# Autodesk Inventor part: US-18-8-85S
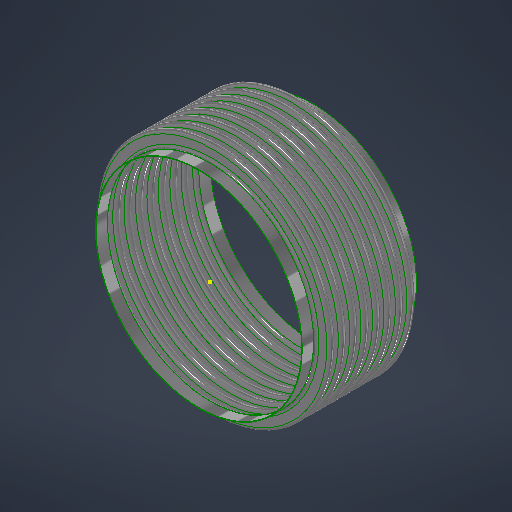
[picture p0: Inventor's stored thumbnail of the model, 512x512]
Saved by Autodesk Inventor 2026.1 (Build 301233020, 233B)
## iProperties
Category: 18 GA (0.048 THICK)
RuleStatus: InUse
Created: 2026-07
Part Number: US-18-8-85S
Project: =STOCK BELLOWS: <Stock Number><SFILL>
Material: ASTM A240-304
Description: =STOCK BELLOWS: <Stock Number>, <SID_> I.D., <SOD_> O.D., <SPLY_> PLY, <Category>, <SNET_CONS> CONS.<PITCH_><STANGENT_> TANGENT<SFILL>
Document SubType Name: Sheet Metal
Designer: LC
Stock Number: U.S-18-8-85S
Surface Area: 659.127 cm^2
Volume: 56.61 cm^3
Sheet Metal Rule: Default
Appearance: STAINLESS STEEL
NET_TUBE: 3.428
COUNTER: 1.500
PBAR: 1.214
PSET: 5.356
PLY: 2
CONS: 2
THK: 0.036
ID: 4.500
OD: 5.500
CONS_: 2
TANGENT: 0.500
PITCH: 0.375
BELLOWS_UPSET: 0.000
NET_CONS: 2
S_CONS: 0
Description_Units: 0
ID_M: 114.30 mm
OD_M: 139.70 mm
THK_M: 0.91 mm
ID_U: 4.500 in
OD_U: 5.500 in
THK_U: 0.036 in
TANGENT2: 0.500
d79: 1.000
d82: 1.000
d83: 26.000
d84: 24.000
d80: 2.571
d81: 10
SID: 2.375
SCONS_: 8
SPITCH: 0.250
SBELLOWS_UPSET: 0.000
SNET_CONS: 8
SS_CONS: 0
SCONS: 8
d174: 8
d177: 0.018
d178: 2.375
d179: 3.000
d180: 0.375
d181: 1.000
d182: 0.000
d190: 8
d191: 1
d192: 1
d193: 8
d194: 0
PART_NUMBER: U.S-18-8-85S
PRESSURE: 85
SIZE: 18.00
STANGENT_: 1.000
d214: 8
d217: 0.030
d218: 6.625
d219: 8.125
d220: 0.500
d221: 1.000
d222: 0.000
d230: 8
d231: 1
d232: 1
d233: 8
d234: 0
STANGENT: 4.000
SPLY_: 1
STHK_: 0.048
SID_: 18.000
SOD_: 20.500
SPITCH_: 1.000
STANGENT__: 1.000
SBELLOWS_UPSET_: 0.000
SDIFF_TAN: 1.000
TAN_TO_TAN: 0.750 in
d252: 2
d275: 2
d287: 0.050
d289: 0.500
d290: 0.000
d263: 2
d265: 1
d268: 2
d269: 0
d286: 2
d288: 1
d291: 2
d292: 0
SOD_NECK: 18 1/8
CFILL: .
SFILL: .
PITCH_: =, <SPITCH_> PITCH,
SREROLL: 0.750
MATTABLE: 20 GA (0.036 THICK)
MESH: ,
CSECT: 2
Author: LC
Keywords: 20 GA (0.036 THICK)
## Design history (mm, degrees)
sketch "Sketch2"
  geometry: L1 (0, -183.595)-(0, 600.956) reference; L2 (58.979, 0)-(57.15, 0); L3 (60.446, -1.467)-(66.554, -1.467); L4 (60.446, -3.296)-(66.554, -3.296); L5 (66.554, -8.058)-(60.446, -8.058); L6 (66.554, -6.229)-(60.446, -6.229); L7 (58.979, -9.525)-(57.15, -9.525); L8 (60.446, 0)-(60.446, -9.525); L9 (66.554, -4.762)-(69.85, -4.763); L10 (57.15, 0)-(57.15, -9.525); L11 (20.376, 102.841)-(20.376, 101.926); L12 (58.262, 488.877)-(58.262, 349.177); L13 (58.262, 479.352)-(58.262, 339.652); L14 (93.133, -58.817)-(93.133, -71.517); L15 (118.746, -66.401)-(118.746, -66.401); L16 (66.554, -6.229)-(66.554, -8.058); L17 (60.446, -6.229)-(60.446, -8.058); L18 (60.446, -7.144)-(66.554, -7.144); L19 (69.85, 0)-(69.85, -9.525); L20 (-66.554, -6.229)-(-66.554, -8.058); L21 (-66.554, -1.467)-(-60.446, -1.467); L22 (-66.554, -3.296)-(-60.446, -3.296); L23 (-60.446, -6.229)-(-66.554, -6.229); L24 (-66.554, -7.144)-(-60.446, -7.144); L25 (-60.446, -8.058)-(-66.554, -8.058); L26 (-60.446, -6.229)-(-60.446, -8.058); L27 (-57.15, -2.522)-(-57.15, -12.047); L28 (-60.446, -4.763)-(-57.15, -4.763); L29 (-66.554, 3.828)-(-66.554, -9.525); L30 (-68.021, 0)-(-69.85, 0); L31 (-69.85, 0)-(-69.85, -9.525); L32 (-68.021, -9.525)-(-69.85, -9.525); A1 r 1.467 centre (60.446, 0) between (58.979, 0) and (60.446, -1.467); A2 r 3.296 centre (60.446, 0) between (57.15, 0) and (60.446, -3.296); A3 r 3.296 centre (66.554, -4.762) between (66.554, -8.058) and (66.554, -1.467); A4 r 1.467 centre (66.554, -4.762) between (66.554, -6.229) and (66.554, -3.296); A5 r 1.467 centre (60.446, -9.525) between (60.446, -8.058) and (58.979, -9.525); A6 r 3.296 centre (60.446, -9.525) between (60.446, -6.229) and (57.15, -9.525); A7 r 2.381 centre (66.554, -4.762) between (66.554, -7.144) and (68.936, -4.762); A8 r 2.381 centre (60.446, -9.525) between (60.446, -7.144) and (58.064, -9.525); A9 r 1.467 centre (-66.554, -9.525) between (-66.554, -8.058) and (-68.021, -9.525); A10 r 1.467 centre (-60.446, -4.763) between (-60.446, -6.229) and (-60.446, -3.296); A11 r 2.381 centre (-60.446, -4.763) between (-60.446, -7.144) and (-58.064, -4.763); A12 r 3.296 centre (-60.446, -4.763) between (-60.446, -8.058) and (-60.446, -1.467); A13 r 2.381 centre (-66.554, -9.525) between (-66.554, -7.144) and (-68.936, -9.525); A14 r 3.296 centre (-66.554, -9.525) between (-66.554, -6.229) and (-69.85, -9.525); A15 r 1.467 centre (-66.554, 0) between (-68.021, 0) and (-66.554, -1.467); A16 r 3.296 centre (-66.554, 0) between (-69.85, 0) and (-66.554, -3.296); 10 further points
  constraints: 62 end point, 38 point on circle, 20 tangent, 16 centre point, 12 parallel, 9 midpoint, 7 vertical, 6 coincident, 6 concentric, 6 point on line, 4 equal radius, 4 perpendicular, 3 horizontal, 1 collinear, 1 horizontal alignment, 10 other
  dimensions: "THK" = 0.9144 distance of L11.start L11.end; "ID" = 114.3 distance of L11.end point (20.376, -12.374); "OD" = 139.7 distance of L12.start L12.end; "PITCH" = 9.525 distance of L12.start L13.start; "TANGENT" = 12.7 distance of L14.start L14.end; "BELLOWS_UPSET" = 0 distance of L15.start L15.end; "d43" = 114.3 diameter of L10 L1 (= ID); "d44" = 139.7 diameter of L9.end L1 (= OD); "d45" = 1.8288 distance between parallel lines of L5 L6 (computed from THK, PLY); "d46" = 3.29565 radius of A3 (computed from PITCH, THK, PLY); "UPSET_PITCH" = 9.525 distance of L2.end L7.end (derived); "SIDEWALL_ANGLE" = 0 deg angle of L3 L9 (derived); "CON_GAP" = 2.9337 distance of point (60.446, -6.229) point (60.446, -3.296) (derived); "TAN1" = 3.74046 dimension on A8 (derived); "TAN2" = 3.74046 dimension on A7 (derived); "LEG1" = 6.1087 distance of L18.start L18.end (derived); "d278" = 1.8288 distance between parallel lines of L25 L23 (derived); "d279" = 3.29565 radius of A12 (derived); "d280" = 9.525 distance of L30.end L31.end (derived); "d281" = 360 deg dimension on L21 L28 (derived); "d282" = 2.9337 distance of point (-66.554, -6.229) point (-66.554, -3.296) (derived); "d283" = 3.74046 dimension on A13 (derived); "d284" = 3.74046 dimension on A11 (derived); "d285" = 6.1087 distance of L24.start L24.end (derived); "d293" = 114.3 diameter of L27 L1 (derived); "d294" = 139.7 diameter of L31 L1 (derived)
  node "Sketch Rectangular Pattern1" dims "d31" = 25.4, "ID" = 114.3
  node "Sketch Rectangular Pattern2" dims "d39" = 25.4, "PITCH" = 9.525
revolve "CONS" stored, may be unused: angle "d48" = 90 deg
node "BELLOW MIDPLANE"
pattern_linear "Rectangular Pattern2" dims "d52" = 9.525 (= UPSET_PITCH)
sketch "Sketch5"
  geometry: C1 r 58.979 at (0, 0) reference; C2 r 57.15 at (0, 0) reference
extrude "TANGENT" new body sketch "Sketch5" distance "d53" = 12.7 (= TANGENT); taper "d54" = 0 deg
revolve "SAMETAN" stored, may be unused: angle "d65" = 90 deg
revolve "DIFFTAN" stored, may be unused: angle "d70" = 90 deg
sketch "Sketch9"
  geometry: L1 (58.391, 0)-(-58.391, 0) reference; L2 (0, -17.78)-(0, 17.78) reference; L3 (41.708, 0)-(-41.708, 0); L4 (41.708, -11.906)-(41.708, 11.906); L5 (29.008, -11.906)-(29.008, 11.906); L6 (15.418, 11.906)-(15.418, -11.906); L7 (-29.008, -11.906)-(-29.008, 11.906); L8 (-41.708, -11.906)-(-41.708, 11.906); L9 (40.914, -11.906)-(40.914, 11.906); L10 (41.708, -11.906)-(40.914, -11.906); L11 (41.708, 11.906)-(40.914, 11.906); L12 (15.815, 11.906)-(15.022, 11.906); L13 (15.022, 11.906)-(15.022, -11.906); L14 (15.022, -11.906)-(15.815, -11.906); L15 (15.815, -11.906)-(15.815, 11.906); L16 (-15.815, 11.906)-(-15.815, -11.906); L17 (-15.418, 11.906)-(-15.418, -11.906); L18 (-15.815, -11.906)-(-15.022, -11.906); L19 (-15.022, -11.906)-(-15.022, 11.906); L20 (-15.022, 11.906)-(-15.815, 11.906); L21 (-41.708, -11.906)-(-40.914, -11.906); L22 (-40.914, -11.906)-(-40.914, 11.906); L23 (-40.914, 11.906)-(-41.708, 11.906); L24 (-41.708, 11.906)-(-41.708, -11.906); L25 (41.708, -0.397)-(-41.708, -0.397); L26 (-41.708, -0.397)-(-41.708, 0.397); L27 (-41.708, 0.397)-(41.708, 0.397); L28 (41.708, 0.397)-(41.708, -0.397); L29 (-41.708, 11.906)-(41.708, 11.906); L30 (41.708, 11.906)-(41.708, 12.7); L31 (41.708, 12.7)-(-41.708, 12.7); L32 (-41.708, 12.7)-(-41.708, 11.906); L33 (41.708, -11.906)-(-41.708, -11.906); L34 (-41.708, -11.906)-(-41.708, -12.7); L35 (-41.708, -12.7)-(41.708, -12.7); L36 (41.708, -12.7)-(41.708, -11.906); 30 further points
  constraints: 68 end point, 13 midpoint, 13 parallel, 8 horizontal, 7 perpendicular, 6 equal length, 3 point on line, 2 vertical, 14 other
  dimensions: "d115" = 23.8125 distance of L4.start L4.end (derived); "d116" = 12.7 distance between parallel lines of L4 L5 (derived); "d117" = 13.58962 distance between parallel lines of L5 L6 (derived); "d125" = 44.42645 distance between parallel lines of L7 L6 (derived); "d127" = 12.7 distance between parallel lines of L8 L7 (derived); "d128" = 26.28962 distance between parallel lines of L6 L4 (derived); "d130" = 83.41607 distance between parallel lines of L8 L4 (derived); "RULER_THK" = 0.79375 distance between parallel lines of L4 L9; "d135" = 0.79375 distance of L13.end L14.end (derived); "d138" = 30.83684 distance of L13.end L16.end (derived); "d143" = 0.79375 distance of L22.end L8.end (derived); "d144" = 0.79375 distance between parallel lines of L27 L25 (derived)
extrude "RULER" join sketch "Sketch9" distance "d149" = 0.79375 (derived); taper "d150" = 0 deg
extrude "BARS" join sketch "Sketch9" distance "d151" = 0.79375 (derived); taper "d152" = 0 deg
pattern_linear "Rectangular Pattern4" dims "d155" = 30.83684 (derived)
sketch "Sketch13"
  geometry: L1 (93.149, -52.467)-(93.149, -77.867); L2 (229.819, 0)-(228.6, 0); L3 (229.819, -25.4)-(228.6, -25.4); L4 (253.39, -19.66)-(235.56, -19.66); L5 (253.39, -18.44)-(235.56, -18.44); L6 (253.39, -12.7)-(260.35, -12.7); L7 (235.56, -5.74)-(253.39, -5.74); L8 (235.56, 0)-(235.56, -25.4); L9 (228.6, 0)-(228.6, -25.4); L10 (58.254, -220.206)-(58.254, -740.906); L11 (58.254, -245.606)-(58.254, -766.306); L12 (58.254, -296.406)-(58.254, -817.106); L13 (58.254, -321.806)-(58.254, -842.506); L14 (58.254, -347.206)-(58.254, -867.906); L15 (58.254, -372.606)-(58.254, -893.306); L16 (58.254, -398.006)-(58.254, -918.706); L17 (58.254, -271.006)-(58.254, -791.706); L18 (20.376, 103.145)-(20.376, 101.926); L19 (235.56, -6.96)-(253.39, -6.96); L20 (0, -1082.436)-(0, 300.742) reference; L21 (-46.99, 0)-(281.94, 0) reference; A1 r 5.74 centre (235.56, 0) between (229.819, 0) and (235.56, -5.74); A2 r 5.74 centre (235.56, -25.4) between (235.56, -19.66) and (229.819, -25.4); A3 r 6.96 centre (235.56, -25.4) between (235.56, -18.44) and (228.6, -25.4); A4 r 5.74 centre (253.39, -12.7) between (253.39, -18.44) and (253.39, -6.96); A5 r 6.96 centre (253.39, -12.7) between (253.39, -19.66) and (253.39, -5.74); A6 r 6.96 centre (235.56, 0) between (228.6, 0) and (235.56, -6.96); 6 further points; 1 other entity
  constraints: 38 end point, 15 point on circle, 9 tangent, 6 centre point, 6 parallel, 5 vertical alignment, 4 point on line, 4 vertical, 3 coincident, 3 concentric, 2 collinear, 2 equal radius, 1 horizontal, 1 perpendicular, 23 other
  dimensions: "SBELLOWS_UPSET_" = 0 distance of point (118.762, -66.401) point (118.762, -66.401); "STOTAL_THK_BELLOW__" = 1.2192 distance between parallel lines of L4 L5 (derived); "d224" = 6.9596 radius of A5 (derived); "d225" = 25.4 distance of L2.end L3.end (derived); "SSIDEWALL_ANGLE_" = 360 deg dimension on L7 L6 (derived); "SSCON_GAP_" = 11.4808 distance of point (235.56, -18.44) point (235.56, -6.96) (derived); "d235" = 457.2 diameter of L9 L20 (derived); "d236" = 520.7 diameter of L6.end L20 (derived)
  node "Sketch Rectangular Pattern4" dims "d228" = 25.4
  node "Sketch Rectangular Pattern5" dims "d229" = 25.4
revolve "SBELLOW" stored, may be unused: angle "d197" = 90 deg
pattern_linear "Rectangular Pattern5" dims "d204" = 25.4 (derived)
revolve "STANGENT" stored, may be unused: angle "d240" = 90 deg
revolve "SSAMETAN" stored, may be unused: angle "d241" = 90 deg
revolve "SDIFFTAN" stored, may be unused: angle "d246" = 90 deg
revolve "INVCON" stored, may be unused: angle "d295" = 90 deg
pattern_linear "Rectangular Pattern6" dims "d298" = 9.525 (derived)
revolve "INVTANGENT" stored, may be unused: angle "d302" = 90 deg
revolve "INVSAMETAN" stored, may be unused: angle "d307" = 90 deg
revolve "INVDIFFTAN" stored, may be unused: angle "d312" = 90 deg
sketch "ID BELLOW MOUNT CALC"
  geometry: L1 (44.45, 0)-(38.1, 0); L2 (38.1, 0)-(38.1, 12.7); L3 (38.1, 12.7)-(44.45, 12.7); L4 (44.45, 12.7)-(44.45, 0); L5 (36.513, 12.7)-(34.684, 12.7); L6 (34.684, 12.7)-(34.684, 0); L7 (34.684, 0)-(36.513, 0); L8 (36.513, 0)-(36.513, 12.7); L9 (0, -2.54)-(0, 15.24) reference; L10 (-8.89, 0)-(53.34, 0) reference; 1 further point
  constraints: 16 end point, 5 parallel, 2 collinear, 2 horizontal, 2 perpendicular
  dimensions: "d314" = 12.7 distance of L5.end L6.end (derived); "d315" = 1.8288 distance of L5.start L5.end (derived); "IG" = 1.5875 distance between parallel lines of L2 L8; "PIPE_OD" = 88.9 diameter of L4 L9; "PIPE_WALL" = 6.35 distance of L2.end L3.end; "ID_MT_BELLOW" = 69.3674 diameter of L6 L9 (derived)
revolve "CFILL" stored, may be unused: angle "d320" = 90 deg
pattern_linear "Rectangular Pattern7" dims "d323" = 9.525 (derived)
revolve "SFILL" stored, may be unused: angle "d324" = 90 deg
pattern_linear "Rectangular Pattern8" dims "d327" = 25.4 (derived)
node "STOCK BELLOW MIDPLANE"
sketch "Sketch21"
  geometry: L1 (0, -100.013)-(0, 100.013) reference; L2 (-100.013, 0)-(100.013, 0) reference; L3 (-0.099, 71.437)-(0.099, 71.437); L4 (0.099, 71.437)-(0.099, 55.562); L5 (0.099, 55.562)-(-0.099, 55.562); L6 (-0.099, 55.562)-(-0.099, 71.437); C1 r 55.562 at (0, 0); C2 r 71.437 at (0, 0); 3 further points
  constraints: 8 end point, 2 centre point, 2 coincident, 2 parallel, 2 tangent, 1 horizontal, 1 perpendicular, 1 other
  dimensions: "d329" = 111.125 diameter of C1 (derived); "d330" = 142.875 diameter of C2 (derived); "d331" = 0.19844 distance of L3.start L3.end
extrude "CLAMSHELL" cut sketch "Sketch21" extent not by distance; stored distance "d332" = 0; taper "d333" = 0 deg
pattern_circular "Circular Pattern1" dims angle "d335" = 180 deg (derived)
node "BELLOW"
sketch "Sketch6"
  geometry: L1 (-19.05, 58.979)-(-6.35, 58.979); L2 (-6.35, 58.979)-(-6.35, 57.15); L3 (-6.35, 57.15)-(-19.05, 57.15); L4 (-19.05, 57.15)-(-19.05, 58.979); L5 (2.54, 0)-(-59.69, 0) reference; L6 (-38.1, -108.388)-(-38.1, 156.601) reference; 1 further point
  constraints: 8 end point, 2 parallel, 1 horizontal, 1 perpendicular
  dimensions: "d61" = 12.7 distance of L2.end L3.end (derived); "d62" = 1.8288 distance of L1.end L2.end (derived); "d63" = 114.3 diameter of L3 L5 (derived); "d64" = 19.05 distance between parallel lines of L4 L6 (derived)
sketch "Sketch12"
  geometry: 1 further point
sketch "Sketch14"
  geometry: L1 (-25.4, 229.819)-(0, 229.819); L2 (0, 229.819)-(0, 228.6); L3 (0, 228.6)-(-25.4, 228.6); L4 (-25.4, 228.6)-(-25.4, 229.819); L5 (5.08, 0)-(-30.48, 0) reference; L6 (0, -40.884)-(0, 245.303) reference; 1 further point
  constraints: 8 end point, 2 parallel, 1 collinear, 1 horizontal, 1 perpendicular
  dimensions: "d237" = 1.2192 distance of L3.end L1.start (derived); "d238" = 457.2 diameter of L3 L5 (derived); "d239" = 25.4 distance of L1.start L1.end (derived); "SOD_NECK" = 459.6384 diameter of L1 L5 (derived)
sketch "Sketch15"
  geometry: L1 (-40.884, 0)-(245.303, 0) reference; L2 (228.6, -203.2)-(229.819, -203.2); L3 (229.819, -203.2)-(229.819, -228.6); L4 (229.819, -228.6)-(228.6, -228.6); L5 (228.6, -228.6)-(228.6, -203.2); L6 (0, -276.86)-(0, 60.96) reference; 1 further point
  constraints: 8 end point, 2 parallel, 1 horizontal, 1 perpendicular
  dimensions: "d205" = 25.4 distance of L4.end L2.start (derived); "d206" = 1.2192 distance of L3.end L4.end (derived); "d207" = 457.2 diameter of L5 L6 (derived); "d208" = 203.2 distance between parallel lines of L1 L2 (derived)
node "TANGENT_"
node "SAME_TAN"
sketch "Sketch8"
  geometry: L1 (58.979, -19.05)-(57.15, -19.05); L2 (57.15, -19.05)-(57.15, -31.75); L3 (57.15, -31.75)-(58.979, -31.75); L4 (58.979, -31.75)-(58.979, -19.05); L5 (0, -40.64)-(0, 21.59) reference; L6 (-108.388, 0)-(156.601, 0) reference; 1 further point
  constraints: 8 end point, 2 parallel, 1 horizontal, 1 perpendicular
  dimensions: "d66" = 114.3 diameter of L2 L5 (derived); "TOTAL_THK_BELLOW" = 1.8288 distance of L2.end L3.end (derived); "d68" = 19.05 distance between parallel lines of L1 L6 (derived); "d69" = 12.7 distance of L1.end L2.end (derived)
node "DIFF_TAN"
node "Sketch Rectangular Pattern3" dims "d138" = 30.83684 (derived), "d141" = 25.4
node "SBELLOW_"
node "STANGENT_"
node "SSAME_TAN"
sketch "Sketch16"
  geometry: L1 (229.819, -203.2)-(228.6, -203.2); L2 (228.6, -203.2)-(228.6, -228.6); L3 (228.6, -228.6)-(229.819, -228.6); L4 (229.819, -228.6)-(229.819, -203.2); L5 (0, -276.86)-(0, 60.96) reference; L6 (-40.884, 0)-(245.303, 0) reference; 1 further point
  constraints: 8 end point, 2 parallel, 1 horizontal, 1 perpendicular
  dimensions: "SDIFF_TAN" = 25.4 distance of L3.end L1.start; "d243" = 1.2192 distance of L2.end L3.end (derived); "d244" = 203.2 distance between parallel lines of L1 L6 (derived); "d245" = 457.2 diameter of L2 L5 (derived)
node "SDIFF_TAN"
body "Solid15"
sketch "Sketch17"
  geometry: L1 (69.85, 12.7)-(68.021, 12.7); L2 (68.021, 12.7)-(68.021, 0); L3 (68.021, 0)-(69.85, 0); L4 (69.85, 0)-(69.85, 12.7); L5 (0, -2.54)-(0, 15.24) reference; L6 (-13.97, 0)-(83.82, 0) reference; 2 further points
  constraints: 8 end point, 2 parallel, 1 horizontal, 1 midpoint, 1 perpendicular, 1 point on line
  dimensions: "INVTANGENT" = 12.7 distance of L3.end L1.start (derived); "d300" = 1.8288 distance of L1.start L1.end (derived); "d301" = 139.7 diameter of L4 L5 (derived)
body "Solid16"
sketch "Sketch18"
  geometry: L1 (69.85, -19.05)-(68.021, -19.05); L2 (68.021, -19.05)-(68.021, -31.75); L3 (68.021, -31.75)-(69.85, -31.75); L4 (69.85, -31.75)-(69.85, -19.05); L5 (-13.97, 0)-(83.82, 0) reference; L6 (0, -40.64)-(0, 21.59) reference; 1 further point
  constraints: 8 end point, 2 parallel, 1 horizontal, 1 perpendicular
  dimensions: "d303" = 19.05 distance between parallel lines of L1 L5 (derived); "d304" = 12.7 distance of L3.end L1.start (derived); "d305" = 1.8288 distance of L2.end L3.end (derived); "d306" = 139.7 diameter of L4 L6 (derived)
body "Solid17"
sketch "Sketch19"
  geometry: L1 (69.85, -19.05)-(68.021, -19.05); L2 (68.021, -19.05)-(68.021, -31.75); L3 (68.021, -31.75)-(69.85, -31.75); L4 (69.85, -31.75)-(69.85, -19.05); L5 (0, -40.64)-(0, 21.59) reference; L6 (-13.97, 0)-(83.82, 0) reference; 1 further point
  constraints: 8 end point, 2 parallel, 1 horizontal, 1 perpendicular
  dimensions: "d308" = 12.7 distance of L1.end L2.end (derived); "d309" = 139.7 diameter of L4 L5 (derived); "d310" = 1.8288 distance of L2.end L3.end (derived); "d311" = 19.05 distance between parallel lines of L1 L6 (derived)
body "Solid18"
body "Solid19"
body "Solid20"
other parameters: "BMPL" = -101.6, "PSET" = 136.0424 (computed from OD, THK, PLY) [user parameter], "PBAR" = 30.83684 (= 0.570796 x PITCH + OD - ID) [user parameter; used in 1 equation term], "COUNTER" = 15 [user parameter], "NET_TUBE" = 87.07367 (computed from CONS_, PBAR, TANGENT) [user parameter], "S_CONS" = 0 [user parameter; used in 1 equation term], "ID_M" = 114.3 (= ID) [user parameter], "OD_M" = 139.7 (= OD) [user parameter], "THK_M" = 0.9144 (= THK) [user parameter], "ID_U" = 114.3 (= ID) [user parameter], "OD_U" = 139.7 (= OD) [user parameter], "THK_U" = 0.9144 (= THK) [user parameter], "D_UNITS" = 0 [user parameter], "TANGENT2" = 12.7 [user parameter], "TAN_TO_TAN" = 19.05 [user parameter], "OD_NECK" = 117.9576 [user parameter], "d79" = 25.4, "d80" = 65.29823 [user parameter], "d82" = 25.4, "d83" = 660.4, "d84" = 609.6, "sa_0" = 4, "FRAME_THK" = 0.79375 [user parameter], "CON_FLAT" = 13.58962 [user parameter], "SID" = 60.325 [user parameter], "SPITCH" = 6.35 [user parameter], "STANGENT_" = 25.4 [user parameter], "SBELLOWS_UPSET" = 0 [user parameter], "SS_CONS" = 0 [user parameter], "STAN_TO_TAN_" = 203.2 [user parameter], "d100" = 1.2192 [user parameter], "d191" = 25.4 [user parameter], "d194" = 0 [user parameter], "STANGENT" = 101.6 [user parameter], "d234" = 0 [user parameter], "SUPSET_PITCH_" = 25.4 [user parameter], "d269" = 0 [user parameter], "d287" = 1.27, "d289" = 12.7, "d290" = 0, "d292" = 0 [user parameter], "Thickness" = 3.048 (derived), "KFactor" = 4.4, "BendRadius" = 3.048 (derived), "BendReliefWidth" = 3.048 (derived), "BendReliefDepth" = 1.524 (derived), "CornerReliefSize" = 12.192 (derived), "SeamGap" = 0.00508, "MinimumRemnant" = 6.096 (derived), "TransitionRadius" = 3.048 (derived), "JacobiRadiusSize" = 3.048 (derived), "GapSize" = 3.048 (derived), "SREROLL" = 19.05 [user parameter], "CUR_STK_PITCH" = 25.4 [user parameter], "d328" = -101.6 (derived), "CSECTDEG" = 180 deg [user parameter]
